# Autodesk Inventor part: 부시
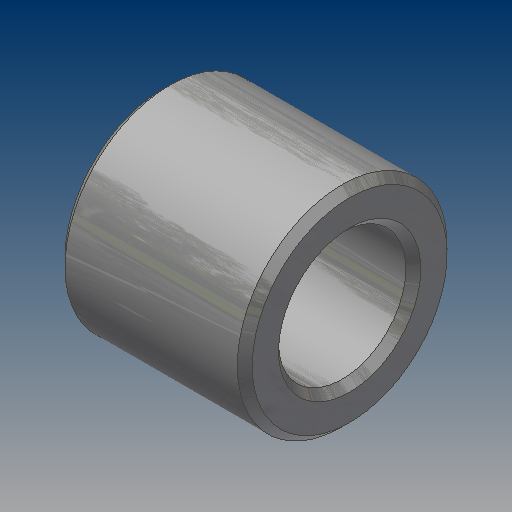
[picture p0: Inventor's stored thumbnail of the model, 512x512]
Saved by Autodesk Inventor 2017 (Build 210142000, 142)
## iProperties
Created: 2016-10
Part Number: 부시
Material: 강철, 연강
Document SubType Name: Modeling
Designer: mduedu
Density: 1 g/cm^3
Appearance: 강철
Author: mduedu
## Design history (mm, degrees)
sketch "스케치1"
  geometry: C1 r 14 at (0, 0); C2 r 8.5 at (0, 0); 1 further point
  constraints: 2 centre point, 2 coincident
  dimensions: "d0" = 28 diameter of C1; "d1" = 17 diameter of C2
extrude "돌출1" new body sketch "스케치1" distance "d2" = 25; taper "d3" = 0 deg
chamfer "모따기1" distance "d4" = 1; stored, may be unused: second distance "d5" = 2, angle "d6" = 45 deg
chamfer "모따기2" distance "d7" = 1; stored, may be unused: second distance "d8" = 2, angle "d9" = 45 deg
node "솔리드1"
